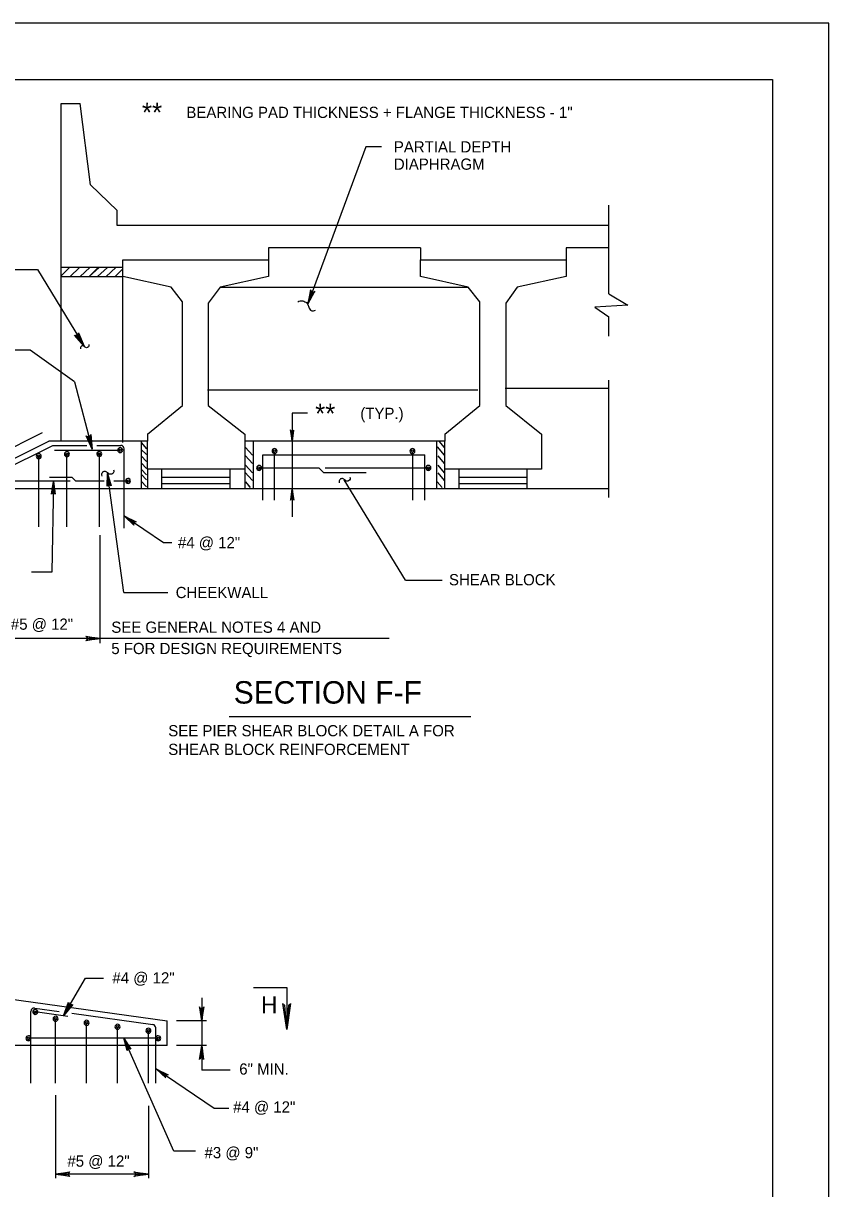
# Model space of a CAD drawing. Extents: x 638091 to 638946, y 298288 to 298882.
# Drawn here: x 638715.9 to 638931.6, y 298569.7 to 298881.5 of the extents above; entities that cross this region are included whole.
import ezdxf

# ---------------------------------------------------------------- set-up
doc = ezdxf.new("R2010")
doc.units = 0
for name, color, linetype in [('2', 7, 'Continuous'), ('40', 7, 'Continuous'), ('PLT-BNDY', 7, 'Continuous')]:
    doc.layers.add(name, color=color, linetype=linetype)

msp = doc.modelspace()

# ---------------------------------------------------------------- linework, layer by layer
at = {"layer": '2'}
for p, q in [((638130.58, 298866.5), (638916.58, 298866.5)), ((638916.58, 298866.5), (638916.58, 298302.5)), ((638726.1, 298860.07), (638731.16, 298860.07)), ((638726.1, 298816.2), (638726.1, 298860.07)), ((638733.97, 298838.32), (638731.16, 298860.07)), ((638807.66, 298848.45), (638792.11, 298806.46)), ((638811.88, 298848.45), (638807.66, 298848.45)), ((638741.1, 298831.38), (638733.97, 298838.32)), ((638741.1, 298827.45), (638741.1, 298831.38)), ((638872.72, 298809.12), (638872.72, 298832.88)), ((638872.72, 298827.45), (638741.1, 298827.45)), ((638822.28, 298821.45), (638781.6, 298821.45)), ((638781.6, 298821.45), (638781.6, 298818.26)), ((638822.28, 298821.45), (638822.28, 298818.26)), ((638861.28, 298821.45), (638861.28, 298818.26)), ((638872.72, 298821.45), (638861.28, 298821.45)), ((638742.6, 298813.76), (638742.6, 298818.26)), ((638742.6, 298818.26), (638781.6, 298818.26)), ((638781.6, 298818.26), (638781.6, 298813.76)), ((638822.28, 298813.76), (638822.28, 298818.26)), ((638822.28, 298818.26), (638861.28, 298818.26)), ((638861.28, 298818.26), (638861.28, 298813.76)), ((638707.59, 298815.66), (638719.77, 298815.66)), ((638719.77, 298815.66), (638732.22, 298795.09)), ((638742.6, 298816.2), (638726.1, 298816.2)), ((638726.1, 298769.7), (638726.1, 298816.2)), ((638726.1, 298813.95), (638728.35, 298816.2)), ((638728.53, 298813.76), (638730.97, 298816.2)), ((638731.16, 298813.76), (638733.78, 298816.2)), ((638733.6, 298813.76), (638736.22, 298816.2)), ((638733.6, 298813.76), (638736.03, 298816.2)), ((638735.85, 298813.76), (638738.47, 298816.2)), ((638738.1, 298813.76), (638740.72, 298816.2)), ((638740.53, 298813.76), (638742.6, 298815.82)), ((638726.1, 298813.76), (638742.6, 298813.76)), ((638742.6, 298769.32), (638742.6, 298813.76)), ((638755.53, 298810.95), (638742.6, 298813.76)), ((638781.6, 298813.76), (638768.66, 298810.95)), ((638835.03, 298810.95), (638822.28, 298813.76)), ((638861.28, 298813.76), (638848.16, 298810.95)), ((638758.53, 298807.01), (638755.53, 298810.95)), ((638768.66, 298810.95), (638765.47, 298806.63)), ((638768.66, 298810.95), (638835.03, 298810.95)), ((638838.22, 298807.01), (638835.03, 298810.95)), ((638848.16, 298810.95), (638845.16, 298806.63)), ((638758.53, 298779.26), (638758.53, 298807.01)), ((638765.47, 298806.63), (638765.47, 298779.26)), ((638838.22, 298779.26), (638838.22, 298807.01)), ((638845.16, 298806.63), (638845.16, 298779.26)), ((638872.72, 298797.82), (638872.72, 298802.94)), ((638717.8, 298794.07), (638711.37, 298794.07)), ((638729.68, 298785.58), (638717.8, 298794.07)), ((638729.68, 298785.58), (638734.4, 298767.56)), ((638837.66, 298783.38), (638765.28, 298783.38)), ((638872.72, 298783.76), (638844.97, 298783.76)), ((638872.72, 298754.67), (638872.72, 298786.05)), ((638749.16, 298771.57), (638758.53, 298779.26)), ((638749.16, 298771.57), (638758.53, 298779.26)), ((638765.47, 298779.26), (638775.22, 298771.57)), ((638792.07, 298777.2), (638787.94, 298777.2)), ((638787.94, 298777.2), (638787.94, 298749.45)), ((638828.85, 298771.57), (638838.22, 298779.26)), ((638845.16, 298779.26), (638854.72, 298771.57)), ((638704.85, 298763.94), (638721.09, 298772)), ((638749.16, 298771.57), (638749.16, 298769.7)), ((638775.22, 298771.57), (638775.22, 298769.7)), ((638828.85, 298771.57), (638828.85, 298769.7)), ((638854.72, 298771.57), (638854.72, 298769.7)), ((638706.51, 298761.63), (638722.75, 298769.7)), ((638709.54, 298761.48), (638723.83, 298768.57)), ((638749.16, 298769.7), (638722.75, 298769.7)), ((638723.83, 298768.57), (638732.95, 298768.57)), ((638735.64, 298768.57), (638742.03, 298768.57)), ((638747.47, 298769.7), (638747.47, 298756.95)), ((638747.47, 298769.32), (638748.97, 298767.63)), ((638749.16, 298762.2), (638749.16, 298769.7)), ((638828.85, 298769.7), (638775.22, 298769.7)), ((638775.22, 298769.7), (638775.22, 298762.2)), ((638775.41, 298768.01), (638777.28, 298765.95)), ((638777.47, 298769.7), (638777.47, 298756.95)), ((638826.6, 298769.7), (638826.6, 298757.13)), ((638826.78, 298768.2), (638828.66, 298765.95)), ((638827.16, 298769.7), (638828.66, 298768.01)), ((638828.85, 298756.95), (638828.85, 298769.7)), ((638828.85, 298762.2), (638828.85, 298769.7)), ((638854.72, 298769.7), (638854.72, 298762.2)), ((638720.07, 298765), (638720.07, 298765.35)), ((638720.08, 298746.77), (638720.08, 298765.67)), ((638724.31, 298767.3), (638741.89, 298767.3)), ((638727.62, 298746.77), (638727.62, 298766.21)), ((638727.62, 298765.54), (638727.62, 298765.9)), ((638736.31, 298765.6), (638736.31, 298765.96)), ((638736.34, 298746.77), (638736.34, 298766.27)), ((638741.88, 298766.63), (638741.88, 298766.98)), ((638742.97, 298746.45), (638742.97, 298767.63)), ((638747.47, 298767.45), (638748.97, 298766.13)), ((638747.47, 298765.76), (638748.97, 298764.26)), ((638747.47, 298765.76), (638748.97, 298764.26)), ((638775.41, 298765.76), (638777.28, 298763.7)), ((638780.1, 298753.95), (638780.1, 298766.05)), ((638780.1, 298766.05), (638823.41, 298766.05)), ((638783.21, 298766.39), (638783.21, 298766.74)), ((638783.24, 298753.95), (638783.24, 298766.32)), ((638820.13, 298766.38), (638820.13, 298766.74)), ((638820.26, 298753.95), (638820.26, 298766.13)), ((638823.41, 298753.95), (638823.41, 298766.05)), ((638826.97, 298765.76), (638828.66, 298763.7)), ((638747.47, 298763.88), (638748.97, 298762.38)), ((638747.47, 298763.88), (638748.97, 298762.38)), ((638747.47, 298762.2), (638748.97, 298760.7)), ((638747.47, 298762.2), (638748.97, 298760.7)), ((638747.47, 298762.01), (638747.47, 298760.7)), ((638749.16, 298762.2), (638749.16, 298757.13)), ((638775.22, 298762.2), (638749.16, 298762.2)), ((638752.91, 298762.2), (638752.91, 298757.13)), ((638771.28, 298762.2), (638771.28, 298757.13)), ((638775.22, 298762.2), (638775.22, 298757.13)), ((638775.41, 298763.32), (638777.28, 298761.26)), ((638779.09, 298762.56), (638795.08, 298762.56)), ((638779.09, 298761.89), (638779.09, 298762.24)), ((638795.08, 298762.56), (638796.28, 298761.36)), ((638796.81, 298762.56), (638824.41, 298762.56)), ((638824.41, 298761.89), (638824.41, 298762.24)), ((638826.97, 298763.32), (638828.66, 298761.26)), ((638854.72, 298762.2), (638828.85, 298762.2)), ((638832.6, 298762.2), (638832.6, 298757.13)), ((638850.78, 298762.2), (638850.78, 298757.13)), ((638708.54, 298759.05), (638728.54, 298759.05)), ((638722.93, 298760.05), (638728.93, 298760.05)), ((638728.93, 298760.05), (638729.93, 298759.05)), ((638729.93, 298759.05), (638737.56, 298759.05)), ((638742.9, 298729.21), (638738.49, 298761.03)), ((638740.23, 298759.05), (638743.98, 298759.05)), ((638743.98, 298758.38), (638743.98, 298758.73)), ((638747.47, 298760.88), (638748.97, 298759.38)), ((638747.47, 298759.01), (638748.97, 298757.51)), ((638771.28, 298759.95), (638752.91, 298759.95)), ((638775.22, 298761.45), (638777.28, 298759.2)), ((638775.41, 298758.82), (638776.72, 298757.32)), ((638796.28, 298761.36), (638807.75, 298761.36)), ((638818.26, 298732.51), (638801.89, 298759.37)), ((638826.78, 298758.82), (638828.1, 298757.32)), ((638826.97, 298761.26), (638828.66, 298759.2)), ((638850.78, 298759.95), (638832.6, 298759.95)), ((638872.72, 298756.95), (638706.51, 298756.95)), ((638771.28, 298758.26), (638752.91, 298758.26)), ((638776.35, 298757.7), (638776.72, 298757.32)), ((638827.72, 298757.7), (638828.1, 298757.32)), ((638850.78, 298758.26), (638832.6, 298758.26)), ((638736.54, 298715.67), (638736.54, 298744.51)), ((638818.26, 298732.51), (638828.06, 298732.51)), ((638742.9, 298729.21), (638754.63, 298729.21)), ((638813.89, 298716.87), (638711.5, 298716.87)), ((638835.79, 298695.97), (638771.04, 298695.97)), ((638777.55, 298623.53), (638786.47, 298623.53)), ((638786.47, 298623.53), (638786.47, 298612.28)), ((638711.53, 298620.57), (638754.44, 298614.58)), ((638763.74, 298620.79), (638763.74, 298614.58)), ((638717.98, 298597.92), (638717.98, 298617.15)), ((638719, 298618.03), (638725.52, 298617.12)), ((638719.08, 298616.33), (638719.13, 298616.69)), ((638727.87, 298615.78), (638719.17, 298617)), ((638724.59, 298615.15), (638724.59, 298615.15)), ((638724.61, 298597.92), (638724.61, 298615.15)), ((638728.9, 298616.65), (638750.64, 298613.61)), ((638724.59, 298614.48), (638724.59, 298614.84)), ((638732.88, 298597.92), (638732.88, 298614.09)), ((638732.88, 298613.42), (638732.88, 298613.77)), ((638741.17, 298597.92), (638741.17, 298613.02)), ((638741.17, 298612.35), (638741.17, 298612.71)), ((638741.84, 298612.94), (638741.84, 298612.94)), ((638749.45, 298597.92), (638749.45, 298611.96)), ((638749.45, 298611.96), (638749.45, 298611.96)), ((638751.41, 298597.92), (638751.41, 298612.73)), ((638754.44, 298608.01), (638754.44, 298614.58)), ((638765.02, 298614.58), (638756.99, 298614.58)), ((638763.74, 298614.58), (638763.74, 298608.01)), ((638752.08, 298609.93), (638717.31, 298609.93)), ((638717.32, 298609.25), (638717.32, 298609.61)), ((638749.46, 298611.29), (638749.46, 298611.64)), ((638752.08, 298609.25), (638752.08, 298609.61)), ((638754.44, 298608.01), (638552.53, 298608.01)), ((638765.02, 298608.01), (638756.99, 298608.01)), ((638763.74, 298608.01), (638763.74, 298601.39)), ((638767.03, 298591.17), (638751.49, 298601.71)), ((638771.31, 298601.39), (638763.74, 298601.39)), ((638724.61, 298594.68), (638724.61, 298572.5)), ((638749.45, 298591.89), (638749.45, 298572.5)), ((638770.95, 298591.17), (638767.03, 298591.17)), ((638749.45, 298573.55), (638724.61, 298573.55))]:
    msp.add_line(p, q, dxfattribs=at)
for points in [[(638792.98, 298809.96), (638793.23, 298809.71), (638792.11, 298806.46), (638792.98, 298809.96), (638792.86, 298810.21), (638792.11, 298806.46), (638793.48, 298809.59), (638793.86, 298809.59), (638792.11, 298806.46), (638793.98, 298809.84), (638793.86, 298809.59)], [(638872.72, 298809.12), (638877.78, 298806.12), (638868.97, 298805.56), (638872.72, 298802.94)], [(638730.71, 298798.45), (638730.53, 298798.15), (638732.22, 298795.09), (638730.71, 298798.45), (638730.77, 298798.72), (638732.22, 298795.09), (638730.32, 298797.96), (638729.93, 298797.99), (638732.22, 298795.09), (638729.65, 298798.05), (638729.93, 298797.99)], [(638733.91, 298771.2), (638733.65, 298770.96), (638734.4, 298767.56), (638733.91, 298771.2), (638734.05, 298771.45), (638734.4, 298767.56), (638733.4, 298770.85), (638733.03, 298770.99), (638734.4, 298767.56), (638732.78, 298771.12), (638733.03, 298770.99)], [(638787.59, 298772.57), (638787.74, 298772.46), (638787.94, 298769.7), (638787.59, 298772.57), (638787.43, 298772.7), (638787.94, 298769.7), (638788.15, 298772.44), (638788.28, 298772.56), (638787.94, 298769.7), (638788.41, 298772.68), (638788.28, 298772.56)], [(638723.57, 298755.71), (638723.81, 298755.77), (638724.08, 298758.92), (638723.57, 298755.71), (638723.48, 298755.56), (638724.08, 298758.92), (638724.18, 298755.85), (638724.36, 298755.64), (638724.08, 298758.92), (638724.51, 298755.55), (638724.36, 298755.64)], [(638738.5, 298757.78), (638738.73, 298757.88), (638738.49, 298761.03), (638738.5, 298757.78), (638738.43, 298757.62), (638738.49, 298761.03), (638739.08, 298758.02), (638739.29, 298757.84), (638738.49, 298761.03), (638739.45, 298757.77), (638739.29, 298757.84)], [(638788.29, 298754.08), (638788.14, 298754.18), (638787.94, 298756.95), (638788.29, 298754.08), (638788.46, 298753.94), (638787.94, 298756.95), (638787.73, 298754.2), (638787.61, 298754.08), (638787.94, 298756.95), (638787.48, 298753.96), (638787.61, 298754.08)], [(638755.72, 298742.51), (638753.47, 298742.51), (638742.97, 298749.63)], [(638745.44, 298747.49), (638745.56, 298747.74), (638743.06, 298749.62), (638745.44, 298747.49), (638745.56, 298747.24), (638743.06, 298749.62), (638745.69, 298747.99), (638745.94, 298748.12), (638743.06, 298749.62), (638746.19, 298748.12), (638745.94, 298748.12)], [(638732.91, 298717.37), (638733.04, 298717.12), (638736.54, 298716.87), (638732.91, 298717.37), (638732.66, 298717.5), (638736.54, 298716.87), (638733.04, 298716.75), (638732.91, 298716.5), (638736.54, 298716.87), (638732.66, 298716.25), (638732.91, 298716.5)], [(638728.92, 298618.87), (638728.56, 298618.88), (638726.68, 298615.95), (638728.92, 298618.87), (638729.19, 298618.95), (638726.68, 298615.95), (638728.3, 298618.98), (638728.14, 298619.34), (638726.68, 298615.95), (638728.06, 298619.61), (638728.14, 298619.34)], [(638763.24, 298618.08), (638763.49, 298617.96), (638763.74, 298614.58), (638763.24, 298618.08), (638763.11, 298618.33), (638763.74, 298614.58), (638763.86, 298617.96), (638764.11, 298618.08), (638763.74, 298614.58), (638764.36, 298618.33), (638764.11, 298618.08)], [(638787.47, 298619.03), (638786.97, 298618.78), (638786.47, 298612.28), (638787.47, 298619.03), (638787.47, 298619.28), (638786.47, 298612.28), (638785.97, 298618.78), (638785.47, 298618.78), (638786.47, 298612.28), (638785.47, 298619.28), (638785.47, 298618.78)], [(638743.8, 298606.8), (638743.99, 298606.96), (638742.89, 298609.93), (638743.8, 298606.8), (638743.78, 298606.63), (638742.89, 298609.93), (638744.28, 298607.2), (638744.54, 298607.08), (638742.89, 298609.93), (638744.71, 298607.06), (638744.54, 298607.08)], [(638762.04, 298579.77), (638756.26, 298579.77), (638742.89, 298609.93)], [(638763.24, 298604.51), (638763.49, 298604.64), (638763.74, 298608.01), (638763.24, 298604.51), (638763.11, 298604.26), (638763.74, 298608.01), (638763.86, 298604.64), (638764.11, 298604.51), (638763.74, 298608.01), (638764.24, 298604.26), (638764.11, 298604.51)], [(638753.96, 298599.57), (638754.08, 298599.82), (638751.58, 298601.7), (638753.96, 298599.57), (638754.08, 298599.32), (638751.58, 298601.7), (638754.21, 298600.07), (638754.46, 298600.2), (638751.58, 298601.7), (638754.71, 298600.2), (638754.46, 298600.2)], [(638728.24, 298573.18), (638728.11, 298573.43), (638724.61, 298573.55), (638728.24, 298573.18), (638728.36, 298572.93), (638724.61, 298573.55), (638728.11, 298573.8), (638728.24, 298574.05), (638724.61, 298573.55), (638728.36, 298574.18), (638728.24, 298574.05)], [(638745.83, 298574.05), (638745.95, 298573.8), (638749.45, 298573.55), (638745.83, 298574.05), (638745.58, 298574.18), (638749.45, 298573.55), (638745.95, 298573.43), (638745.83, 298573.18), (638749.45, 298573.55), (638745.58, 298572.93), (638745.83, 298573.18)]]:
    msp.add_lwpolyline(points, dxfattribs=at)
for centre in [(638720.08, 298765.67), (638727.62, 298766.21), (638736.3, 298766.27), (638741.89, 298767.3), (638783.21, 298767.06), (638820.13, 298767.05), (638779.09, 298762.56), (638824.41, 298762.56), (638743.98, 298759.05), (638719.17, 298617), (638724.59, 298615.15), (638732.88, 298614.09), (638741.17, 298613.02), (638749.45, 298611.96), (638717.31, 298609.93), (638752.08, 298609.93)]:
    msp.add_circle(centre, 0.314, dxfattribs=at)
for centre, radius, start, end in [((638741.89, 298767.3), 0.671, 269.6129, 268.6063), ((638742.03, 298767.68), 0.891, 0, 90), ((638720.08, 298765.67), 0.671, 269.6129, 268.6063), ((638727.62, 298766.21), 0.671, 269.6129, 268.6063), ((638736.3, 298766.27), 0.671, 271.3937, 270.3871), ((638783.21, 298767.06), 0.671, 269.6129, 268.6063), ((638820.13, 298767.05), 0.671, 269.6129, 268.6063), ((638779.09, 298762.56), 0.671, 269.6129, 268.6063), ((638824.41, 298762.56), 0.671, 269.6129, 268.6063), ((638743.98, 298759.05), 0.671, 271.3937, 270.3871), ((638718.87, 298617.15), 0.891, 82.051, 180), ((638719.17, 298617), 0.671, 263.4446, 262.438), ((638724.59, 298615.15), 0.671, 269.6129, 268.6063), ((638732.88, 298614.09), 0.671, 271.3937, 270.3871), ((638741.17, 298613.02), 0.671, 271.3937, 270.3871), ((638749.45, 298611.96), 0.671, 271.3937, 270.3871), ((638750.52, 298612.73), 0.891, 0, 82.0509), ((638717.31, 298609.93), 0.671, 271.3937, 270.3871), ((638752.08, 298609.93), 0.671, 269.6129, 268.6063)]:
    msp.add_arc(centre, radius, start, end, dxfattribs=at)
for points in [[(638789.48, 298807.02), (638790.05, 298807.21), (638790.8, 298807.21), (638791.36, 298807.02), (638791.73, 298806.83), (638792.11, 298806.27), (638792.48, 298805.33), (638792.86, 298804.77), (638793.61, 298804.58), (638794.17, 298804.77)], [(638733.46, 298795.53), (638733.49, 298795.14), (638733.18, 298794.74), (638732.52, 298794.81), (638732.21, 298795.1), (638731.66, 298795.21), (638731.43, 298795.06), (638731.26, 298794.76), (638731.29, 298794.37)], [(638740.1, 298762.05), (638740.15, 298761.48), (638739.71, 298760.91), (638738.75, 298761.01), (638738.3, 298761.43), (638737.51, 298761.59), (638737.18, 298761.38), (638736.93, 298760.94), (638736.98, 298760.38)], [(638803.38, 298760.08), (638803.42, 298759.57), (638803.03, 298759.05), (638802.17, 298759.14), (638801.76, 298759.52), (638801.05, 298759.66), (638800.75, 298759.47), (638800.52, 298759.08), (638800.56, 298758.57)]]:
    msp.add_spline(points, degree=3, dxfattribs=at)
at = {"layer": '40'}
for p, q in [((638724.08, 298758.92), (638723.56, 298734.69)), ((638723.56, 298734.69), (638718.16, 298734.69)), ((638726.68, 298615.95), (638732.63, 298626.04)), ((638732.63, 298626.04), (638737.41, 298626.04))]:
    msp.add_line(p, q, dxfattribs=at)
at = {"layer": 'PLT-BNDY'}
msp.add_lwpolyline([(638090.58, 298287.5), (638931.58, 298287.5), (638931.58, 298881.5), (638090.58, 298881.5)], close=True, dxfattribs=at)

# ---------------------------------------------------------------- texts
at = {"layer": '2'}
for s, height, p in [('**', 5.184, (638747.72, 298855.07)), ('BEARING PAD THICKNESS + FLANGE THICKNESS - 1"', 3, (638759.61, 298856.17)), ('PARTIAL DEPTH', 3, (638815.16, 298846.95)), ('DIAPHRAGM', 3, (638815.16, 298842.32)), ('**', 5.184, (638794.1, 298774.51)), ('(TYP.)', 3, (638806.18, 298775.65)), ('#4 @ 12"', 3, (638757.36, 298741.07)), ('SHEAR BLOCK ', 3, (638829.92, 298731.14)), ('CHEEKWALL', 3, (638756.75, 298727.71)), ('#5 @ 12"', 3, (638712.63, 298719.25)), ('SEE GENERAL NOTES 4 AND', 2.9999, (638739.51, 298718.43)), ('5 FOR DESIGN REQUIREMENTS', 2.9999, (638739.51, 298712.73)), ('SECTION F-F', 6.0003, (638772.29, 298699.49)), ('SEE PIER SHEAR BLOCK DETAIL A FOR', 3, (638754.76, 298690.74)), ('SHEAR BLOCK REINFORCEMENT', 3, (638754.76, 298685.74)), ('#4 @ 12"', 3, (638739.81, 298624.6)), ('H', 4.5, (638779.62, 298616.63)), ('6" MIN.', 3, (638773.77, 298600.22)), ('#4 @ 12"', 3, (638772.13, 298590.07)), ('#3 @ 9"', 3, (638764.47, 298577.85)), ('#5 @ 12"', 3, (638727.76, 298575.58))]:
    msp.add_text(s, height=height, dxfattribs=at).set_placement(p)

doc.saveas('drawing.dxf')
